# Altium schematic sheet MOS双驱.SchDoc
size A4
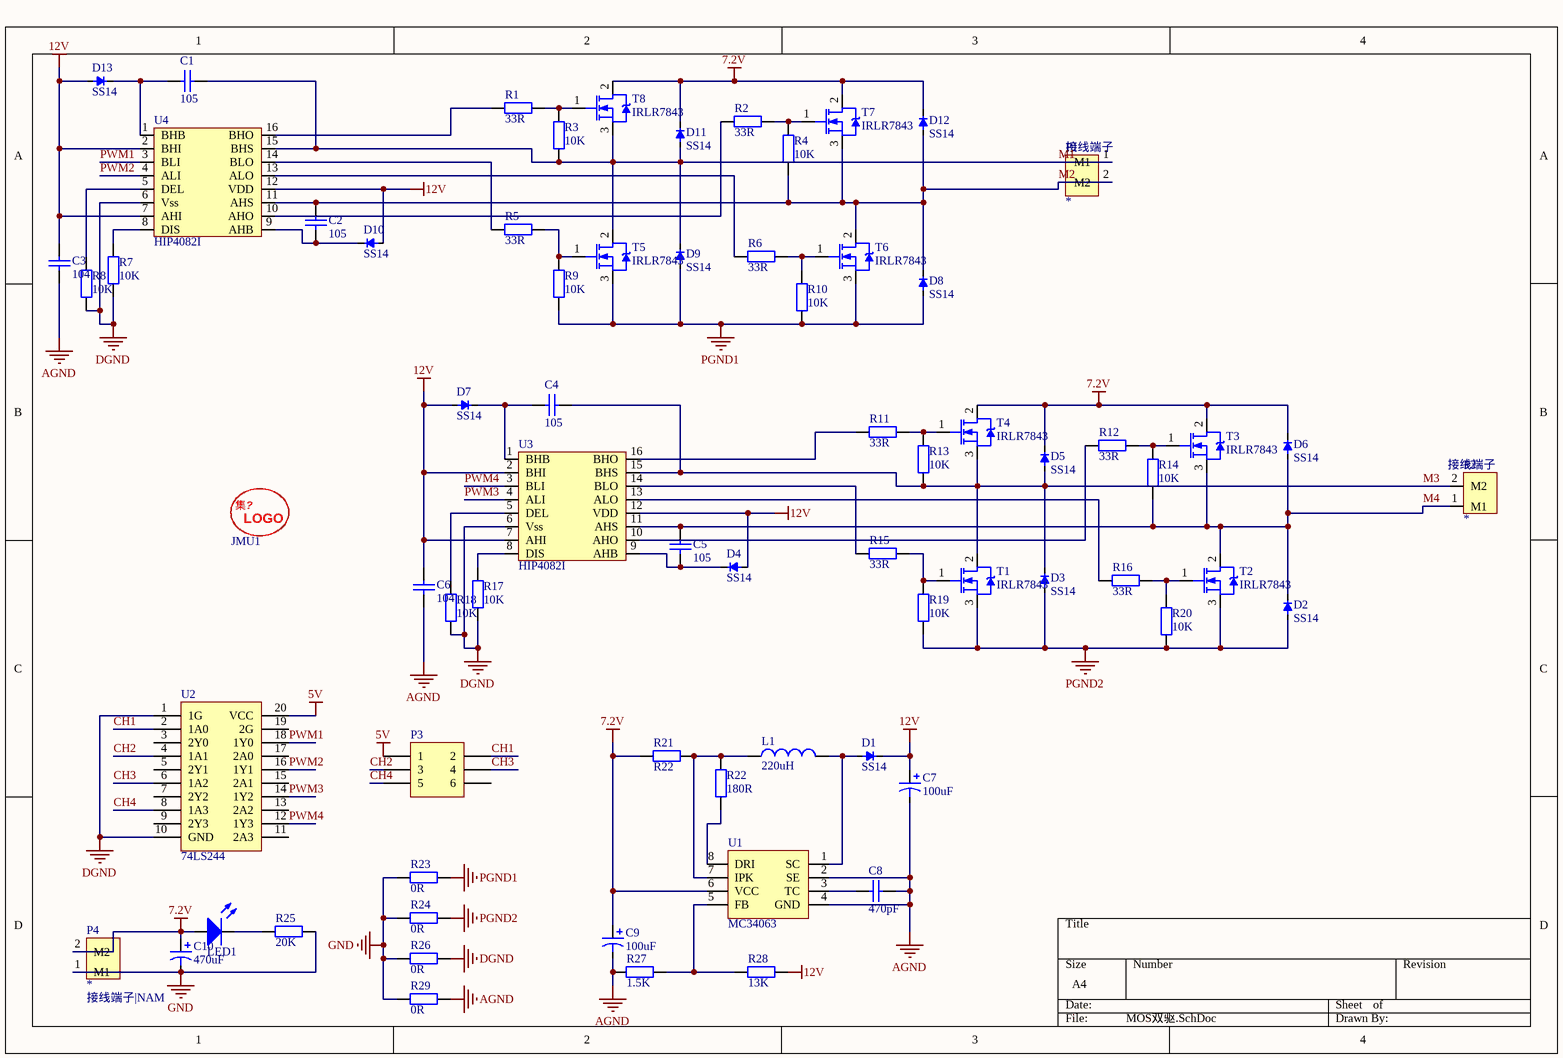
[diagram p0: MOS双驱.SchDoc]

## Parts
C1  105  [0805]
C2  105  [0805]
C3  104  [0805]
C4  105  [0805]
C5  105  [0805]
C6  104  [0805]
C7  100uF  [ED6.3]
C8  470pF  [0805]
C9  100uF  [Pol Cap(220uF)]
C10  470uF  [ED8]
D1  SS14  [二极管]
D2  SS14  [二极管]
D3  SS14  [二极管]
D4  SS14  [二极管]
D5  SS14  [二极管]
D6  SS14  [二极管]
D7  SS14  [二极管]
D8  SS14  [二极管]
D9  SS14  [二极管]
D10  SS14  [二极管]
D11  SS14  [二极管]
D12  SS14  [二极管]
D13  SS14  [二极管]
JMU1  JMU  [JMU_logo（1）]  (value not drawn)
L1  220uH  [电感（220uh）]
LED1  LED  [LED(0805)]  (value not drawn)
P1  *  [接线端子]
P2  *  [接线端子]
P3  Header 3X2  [HDR2X3]  (value not drawn)
P4  *  [接线端子]
R1  33R  [0603]
R2  33R  [0603]
R3  10K  [0603]
R4  10K  [0603]
R5  33R  [0603]
R6  33R  [0603]
R7  10K  [0603]
R8  10K  [0603]
R9  10K  [0603]
R10  10K  [0603]
R11  33R  [0603]
R12  33R  [0603]
R13  10K  [0603]
R14  10K  [0603]
R15  33R  [0603]
R16  33R  [0603]
R17  10K  [0603]
R18  10K  [0603]
R19  10K  [0603]
R20  10K  [0603]
R21  R22  [0805]
R22  180R  [0805]
R23  0R  [0805]
R24  0R  [0805]
R25  20K  [0805]
R26  0R  [0805]
R27  1.5K  [0805]
R28  13K  [0805]
R29  0R  [0805]
T1  IRLR7843  [IRLR7843(MOS)]
T2  IRLR7843  [IRLR7843(MOS)]
T3  IRLR7843  [IRLR7843(MOS)]
T4  IRLR7843  [IRLR7843(MOS)]
T5  IRLR7843  [IRLR7843(MOS)]
T6  IRLR7843  [IRLR7843(MOS)]
T7  IRLR7843  [IRLR7843(MOS)]
T8  IRLR7843  [IRLR7843(MOS)]
U1  MC34063  [MA34063]
U2  74LS244  [74LS244D]
U3  HIP4082I  [HIP4082I]
U4  HIP4082I  [HIP4082I]

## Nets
5V: P3.1 U2.20(VCC)
7.2V: C9.1 C10.1 D5.2(-) D6.2(-) D11.2(-) D12.2(-) LED1.1(A) P4.2(M2) R21.2 T3.2(D) T4.2(D) T7.2(D) T8.2(D) U1.6(VCC)
12V: C3.2 C6.2 C7.1 D1.2(-) D4.1(+) D7.1(+) D10.1(+) D13.1(+) R28.2 U3.2(BHI) U3.7(AHI) U3.12(VDD) U4.2(BHI) U4.7(AHI) U4.12(VDD)
AGND: C3.1 C6.1 C7.2 C8.1 C9.2 R27.1 R29.2 U1.2(SE) U1.4(GND)
DGND: R7.1 R8.1 R17.1 R18.1 R26.2 U2.1(1G) U2.10(GND) U3.6(Vss) U4.6(Vss)
GND: C10.2 P4.1(M1) R23.1 R24.1 R25.2 R26.1 R29.1
PGND1: D8.1(+) D9.1(+) R9.1 R10.1 R23.2 T5.3(S) T6.3(S)
PGND2: D2.1(+) D3.1(+) R19.1 R20.1 R24.2 T1.3(S) T2.3(S)
CH1: P3.2 U2.2(1A0)
CH2: P3.3 U2.4(1A1)
CH3: P3.4 U2.6(1A2)
CH4: P3.5 U2.8(1A3)
M1: C1.2 D9.2(-) D11.1(+) P1.1(M1) R3.1 T5.2(D) T8.3(S) U4.15(BHS)
M2: C2.2 D8.2(-) D12.1(+) P1.2(M2) R4.1 T6.2(D) T7.3(S) U4.11(AHS)
M3: C4.2 D3.2(-) D5.1(+) P2.2(M2) R13.1 T1.2(D) T4.3(S) U3.15(BHS)
M4: C5.2 D2.2(-) D6.1(+) P2.1(M1) R14.1 T2.2(D) T3.3(S) U3.11(AHS)
PWM1: U2.18(1Y0) U4.3(BLI)
PWM2: U2.16(1Y1) U4.4(ALI)
PWM3: U2.14(1Y2) U3.4(ALI)
PWM4: U2.12(1Y3) U3.3(BLI)
NetC1_1: C1.1 D13.2(-) U4.1(BHB)
NetC2_1: C2.1 D10.2(-) U4.9(AHB)
NetC4_1: C4.1 D7.2(-) U3.1(BHB)
NetC5_1: C5.1 D4.2(-) U3.9(AHB)
NetC8_2: C8.2 U1.3(TC)
NetD1_1: D1.1(+) L1.2 U1.1(SC)
NetL1_1: L1.1 R21.1 R22.2 U1.7(IPK)
NetLED1_2: LED1.2(K) R25.1
NetR1_1: R1.1 R3.2 T8.1(G)
NetR1_2: R1.2 U4.16(BHO)
NetR2_1: R2.1 R4.2 T7.1(G)
NetR2_2: R2.2 U4.10(AHO)
NetR5_1: R5.1 R9.2 T5.1(G)
NetR5_2: R5.2 U4.14(BLO)
NetR6_1: R6.1 R10.2 T6.1(G)
NetR6_2: R6.2 U4.13(ALO)
NetR7_2: R7.2 U4.8(DIS)
NetR8_2: R8.2 U4.5(DEL)
NetR11_1: R11.1 R13.2 T4.1(G)
NetR11_2: R11.2 U3.16(BHO)
NetR12_1: R12.1 R14.2 T3.1(G)
NetR12_2: R12.2 U3.10(AHO)
NetR15_1: R15.1 R19.2 T1.1(G)
NetR15_2: R15.2 U3.14(BLO)
NetR16_1: R16.1 R20.2 T2.1(G)
NetR16_2: R16.2 U3.13(ALO)
NetR17_2: R17.2 U3.8(DIS)
NetR18_2: R18.2 U3.5(DEL)
NetR22_1: R22.1 U1.8(DRI)
NetR27_2: R27.2 R28.1 U1.5(FB)

Not connected (* = marked no-connect by the designer): P3 6; U2 3(2Y0) 5(2Y1) 7(2Y2) 9(2Y3) 11(2A3) 13(2A2) 15(2A1) 17(2A0) 19(2G)

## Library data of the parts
C1-C6 C8 = Cap: 无极电容; Value: 10uF
C7 C9 = pol cap: 通用有极电容; value: 22uF
C10 = 固态贴片电容: ED8:470UF  ED6.3:100UF
D1-D13 = IN5819
JMU1 = JMU-LOGO
L1 = 电感 220uh: 7*7*4
LED1 = LED: 发光二极管
P1 P2 P4 = 接线端子
P3 = Header 3X2: Header, 3-Pin, Dual row
R1 R2 R5 R6 R11 R12 R15 R16 R21-R29 = Res: 通用电阻; Value: 10K
R3 R4 R7-R10 R13 R14 R17-R20 = Res: 通用电阻
T1-T8 = N_MOS(I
